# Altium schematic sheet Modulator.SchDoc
size A4; Organization: Altium Limited; Address1: L3, 12a Rodborough Rd; Address2: Frenchs Forest; Address3: NSW; Address4: Australia 2086
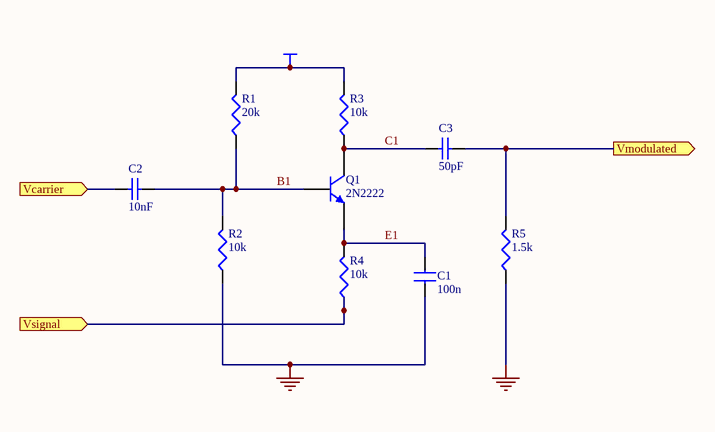
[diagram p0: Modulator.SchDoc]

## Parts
C1  100n
C2  10nF  [RAD-0.3]
C3  50pF  [RAD-0.3]
Q1  2N2222  [AXIAL-0.3]
R1  20k
R2  10k
R3  10k
R4  10k
R5  1.5k

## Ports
Vcarrier (in), Vmodulated (out), Vsignal (in)

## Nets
GND: C1.1 R2.2(BOT) R5.2(BOT)
VCC: R1.1(TOP) R3.1(TOP)
B1: C2.2 Q1.2(B) R1.2(BOT) R2.1(TOP)
C1: C3.1 Q1.3(C) R3.2(BOT)
E1: C1.2 Q1.1(E) R4.1(TOP)
Vcarrier: C2.1 ; port Vcarrier
Vmodulated: C3.2 R5.1(TOP) ; port Vmodulated
Vsignal: R4.2(BOT) ; port Vsignal

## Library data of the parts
C1 = CAP: Capacitor
C2 C3 = Cap: Capacitor; Manufacturer: Generic Components; Class I: Passive
Q1 = 2N2222: General Purpose Transistor NPN Silicon; Manufacturer: Motorola; Package Information: Latest Revision: 1997; Class I: Discrete; Class II: BJT - Low Power
R1-R5 = RES: Resistor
